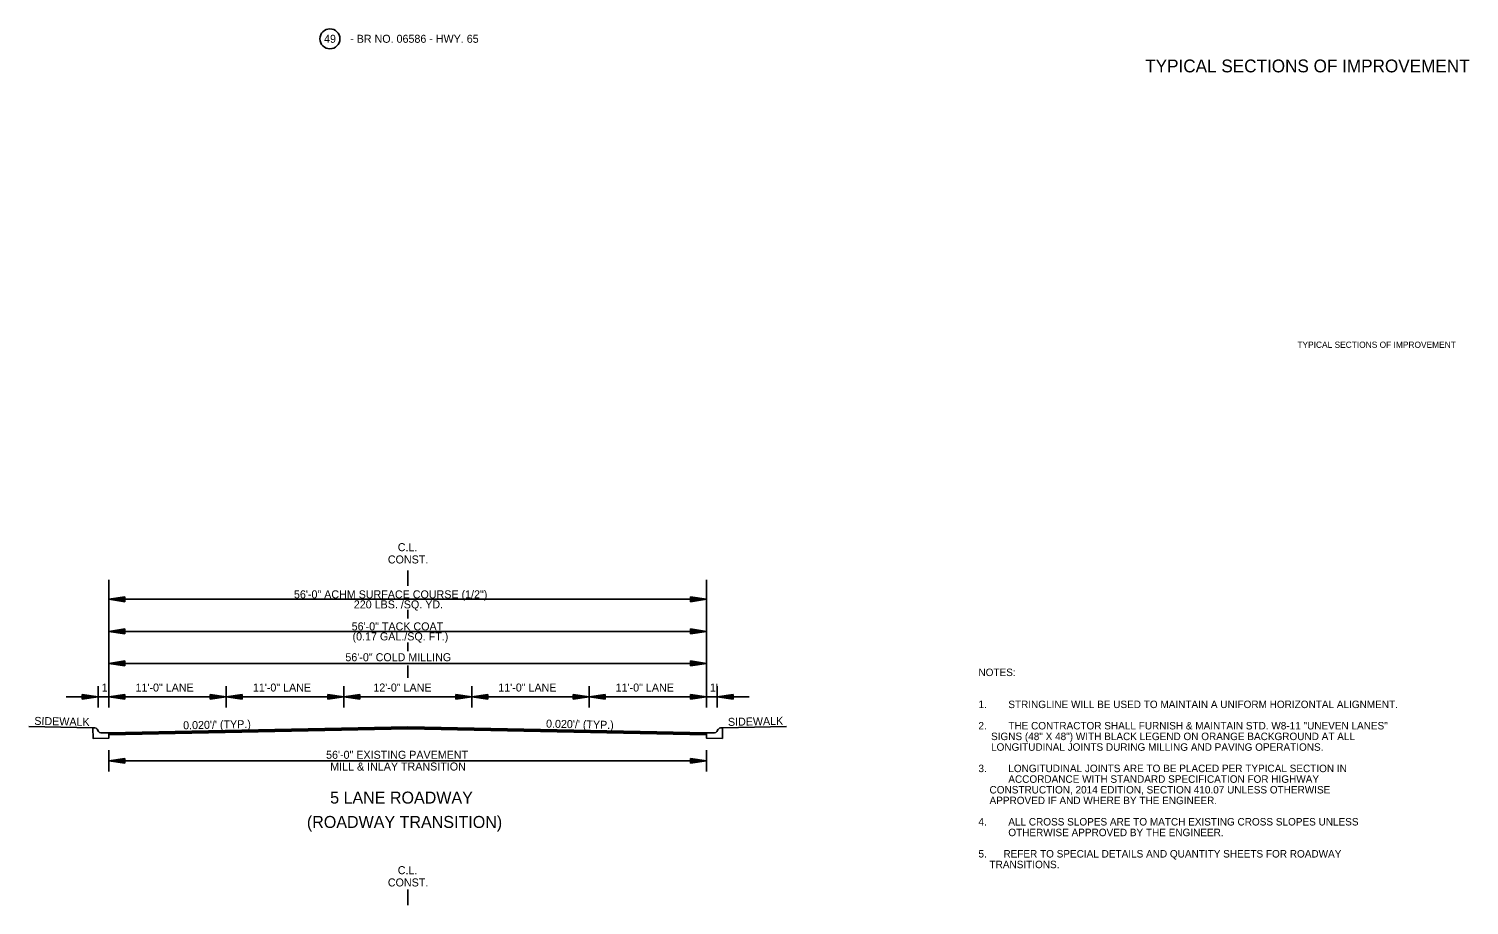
# Model space of a CAD drawing. Extents: x 550980 to 1930787, y -1972975 to 596640.
# Drawn here: x 551196 to 552546, y -1967506 to -1966685 of the extents above; entities that cross this region are included whole.
import ezdxf

# ---------------------------------------------------------------- set-up
doc = ezdxf.new("R2010")
doc.units = 0
for name, color, linetype in [('R_Border', 7, 'Continuous'), ('R_Border Notes', 7, 'Continuous'), ('R_Draft', 7, 'Continuous'), ('S_AREA_CALC', 7, 'Continuous')]:
    doc.layers.add(name, color=color, linetype=linetype)

# ---------------------------------------------------------------- blocks, each defined once
blk = doc.blocks.new('BPPOLY')
at = {"layer": 'R_Border'}
blk.add_circle((0, 0), 9.34, dxfattribs=at)

msp = doc.modelspace()

# ---------------------------------------------------------------- linework, layer by layer
at = {"layer": 'R_Border'}
for p, q in [((551551.1, -1967192), (551551.1, -1967206.5)), ((551286.1, -1967216.7), (551271.1, -1967219)), ((551271.1, -1967219), (551831.1, -1967219)), ((551286.1, -1967221.2), (551271.1, -1967219)), ((551286.1, -1967217.1), (551273.6, -1967219)), ((551286.1, -1967220.9), (551273.6, -1967219)), ((551286.1, -1967217.5), (551276.2, -1967219)), ((551286.1, -1967220.5), (551276.2, -1967219)), ((551286.1, -1967217.9), (551278.7, -1967219)), ((551286.1, -1967220.1), (551278.7, -1967219)), ((551286.1, -1967218.2), (551281.2, -1967219)), ((551286.1, -1967219.7), (551281.2, -1967219)), ((551286.1, -1967218.6), (551283.7, -1967219)), ((551286.1, -1967219.3), (551283.7, -1967219)), ((551286.1, -1967221.2), (551286.1, -1967216.7)), ((551816.1, -1967216.7), (551831.1, -1967219)), ((551816.1, -1967216.7), (551816.1, -1967221.2)), ((551816.1, -1967217.1), (551828.6, -1967219)), ((551816.1, -1967217.5), (551826, -1967219)), ((551816.1, -1967217.9), (551823.5, -1967219)), ((551816.1, -1967218.3), (551821, -1967219)), ((551816.1, -1967218.6), (551818.5, -1967219)), ((551816.1, -1967221.2), (551831.1, -1967219)), ((551816.1, -1967219.7), (551821, -1967219)), ((551816.1, -1967220.5), (551826, -1967219)), ((551816.1, -1967220.9), (551828.6, -1967219)), ((551816.1, -1967220.1), (551823.5, -1967219)), ((551816.1, -1967219.3), (551818.5, -1967219)), ((551551.1, -1967228.9), (551551.1, -1967237.1)), ((551286.1, -1967246.7), (551271.1, -1967249)), ((551286.1, -1967247.1), (551273.6, -1967249)), ((551286.1, -1967247.5), (551276.2, -1967249)), ((551286.1, -1967247.9), (551278.7, -1967249)), ((551286.1, -1967248.2), (551281.2, -1967249)), ((551286.1, -1967251.2), (551286.1, -1967246.7)), ((551816.1, -1967246.7), (551831.1, -1967249)), ((551816.1, -1967246.7), (551816.1, -1967251.2)), ((551816.1, -1967247.1), (551828.6, -1967249)), ((551816.1, -1967247.5), (551826, -1967249)), ((551816.1, -1967247.9), (551823.5, -1967249)), ((551816.1, -1967248.3), (551821, -1967249)), ((551271.1, -1967249), (551831.1, -1967249)), ((551286.1, -1967251.2), (551271.1, -1967249)), ((551286.1, -1967250.9), (551273.6, -1967249)), ((551286.1, -1967250.5), (551276.2, -1967249)), ((551286.1, -1967250.1), (551278.7, -1967249)), ((551286.1, -1967249.7), (551281.2, -1967249)), ((551286.1, -1967248.6), (551283.7, -1967249)), ((551286.1, -1967249.3), (551283.7, -1967249)), ((551551.1, -1967259.4), (551551.1, -1967267.6)), ((551816.1, -1967248.6), (551818.5, -1967249)), ((551816.1, -1967251.2), (551831.1, -1967249)), ((551816.1, -1967249.7), (551821, -1967249)), ((551816.1, -1967250.5), (551826, -1967249)), ((551816.1, -1967250.9), (551828.6, -1967249)), ((551816.1, -1967250.1), (551823.5, -1967249)), ((551816.1, -1967249.3), (551818.5, -1967249)), ((551271.1, -1967279), (551831.1, -1967279)), ((551261.1, -1967300.4), (551261.1, -1967320.4)), ((551381.1, -1967300.4), (551381.1, -1967320.4)), ((551491.1, -1967300.4), (551491.1, -1967320.4)), ((551611.1, -1967300.4), (551611.1, -1967320.4)), ((551721.1, -1967300.4), (551721.1, -1967320.4)), ((551841.1, -1967300.4), (551841.1, -1967320.4)), ((551231.1, -1967310.4), (551871.1, -1967310.4)), ((551246.1, -1967308.1), (551261.1, -1967310.4)), ((551246.1, -1967308.1), (551246.1, -1967312.6)), ((551246.1, -1967308.5), (551258.6, -1967310.4)), ((551246.1, -1967308.9), (551256, -1967310.4)), ((551246.1, -1967309.3), (551253.5, -1967310.4)), ((551246.1, -1967309.7), (551251, -1967310.4)), ((551246.1, -1967310), (551248.5, -1967310.4)), ((551246.1, -1967312.6), (551261.1, -1967310.4)), ((551246.1, -1967311.1), (551251, -1967310.4)), ((551246.1, -1967311.9), (551256, -1967310.4)), ((551246.1, -1967312.3), (551258.6, -1967310.4)), ((551246.1, -1967311.5), (551253.5, -1967310.4)), ((551246.1, -1967310.7), (551248.5, -1967310.4)), ((551286.1, -1967308.1), (551271.1, -1967310.4)), ((551286.1, -1967312.6), (551271.1, -1967310.4)), ((551286.1, -1967308.5), (551273.6, -1967310.4)), ((551286.1, -1967312.3), (551273.6, -1967310.4)), ((551286.1, -1967308.9), (551276.2, -1967310.4)), ((551286.1, -1967311.9), (551276.2, -1967310.4)), ((551286.1, -1967309.3), (551278.7, -1967310.4)), ((551286.1, -1967311.5), (551278.7, -1967310.4)), ((551286.1, -1967309.7), (551281.2, -1967310.4)), ((551286.1, -1967311.1), (551281.2, -1967310.4)), ((551286.1, -1967310), (551283.7, -1967310.4)), ((551286.1, -1967310.7), (551283.7, -1967310.4)), ((551286.1, -1967312.6), (551286.1, -1967308.1)), ((551366.1, -1967308.1), (551381.1, -1967310.4)), ((551366.1, -1967308.1), (551366.1, -1967312.6)), ((551366.1, -1967308.5), (551378.6, -1967310.4)), ((551366.1, -1967308.9), (551376, -1967310.4)), ((551366.1, -1967309.3), (551373.5, -1967310.4)), ((551366.1, -1967309.7), (551371, -1967310.4)), ((551366.1, -1967310), (551368.5, -1967310.4)), ((551366.1, -1967312.6), (551381.1, -1967310.4)), ((551366.1, -1967311.1), (551371, -1967310.4)), ((551366.1, -1967311.9), (551376, -1967310.4)), ((551366.1, -1967312.3), (551378.6, -1967310.4)), ((551366.1, -1967311.5), (551373.5, -1967310.4)), ((551366.1, -1967310.7), (551368.5, -1967310.4)), ((551396.1, -1967308.1), (551381.1, -1967310.4)), ((551396.1, -1967312.6), (551381.1, -1967310.4)), ((551396.1, -1967308.5), (551383.6, -1967310.4)), ((551396.1, -1967312.3), (551383.6, -1967310.4)), ((551396.1, -1967308.9), (551386.2, -1967310.4)), ((551396.1, -1967311.9), (551386.2, -1967310.4)), ((551396.1, -1967309.3), (551388.7, -1967310.4)), ((551396.1, -1967311.5), (551388.7, -1967310.4)), ((551396.1, -1967309.7), (551391.2, -1967310.4)), ((551396.1, -1967311.1), (551391.2, -1967310.4)), ((551396.1, -1967310), (551393.7, -1967310.4)), ((551396.1, -1967310.7), (551393.7, -1967310.4)), ((551396.1, -1967312.6), (551396.1, -1967308.1)), ((551476.1, -1967308.1), (551491.1, -1967310.4)), ((551476.1, -1967308.1), (551476.1, -1967312.6)), ((551476.1, -1967308.5), (551488.6, -1967310.4)), ((551476.1, -1967308.9), (551486, -1967310.4)), ((551476.1, -1967309.3), (551483.5, -1967310.4)), ((551476.1, -1967309.7), (551481, -1967310.4)), ((551476.1, -1967310), (551478.5, -1967310.4)), ((551476.1, -1967312.6), (551491.1, -1967310.4)), ((551476.1, -1967311.1), (551481, -1967310.4)), ((551476.1, -1967311.9), (551486, -1967310.4)), ((551476.1, -1967312.3), (551488.6, -1967310.4)), ((551476.1, -1967311.5), (551483.5, -1967310.4)), ((551476.1, -1967310.7), (551478.5, -1967310.4)), ((551506.1, -1967308.1), (551491.1, -1967310.4)), ((551506.1, -1967312.6), (551491.1, -1967310.4)), ((551506.1, -1967308.5), (551493.6, -1967310.4)), ((551506.1, -1967312.3), (551493.6, -1967310.4)), ((551506.1, -1967308.9), (551496.2, -1967310.4)), ((551506.1, -1967311.9), (551496.2, -1967310.4)), ((551506.1, -1967309.3), (551498.7, -1967310.4)), ((551506.1, -1967311.5), (551498.7, -1967310.4)), ((551506.1, -1967309.7), (551501.2, -1967310.4)), ((551506.1, -1967311.1), (551501.2, -1967310.4)), ((551506.1, -1967310), (551503.7, -1967310.4)), ((551506.1, -1967310.7), (551503.7, -1967310.4)), ((551506.1, -1967312.6), (551506.1, -1967308.1)), ((551596.1, -1967308.1), (551611.1, -1967310.4)), ((551596.1, -1967308.1), (551596.1, -1967312.6)), ((551596.1, -1967308.5), (551608.6, -1967310.4)), ((551596.1, -1967308.9), (551606, -1967310.4)), ((551596.1, -1967309.3), (551603.5, -1967310.4)), ((551596.1, -1967309.7), (551601, -1967310.4)), ((551596.1, -1967310), (551598.5, -1967310.4)), ((551596.1, -1967312.6), (551611.1, -1967310.4)), ((551596.1, -1967311.1), (551601, -1967310.4)), ((551596.1, -1967311.9), (551606, -1967310.4)), ((551596.1, -1967312.3), (551608.6, -1967310.4)), ((551596.1, -1967311.5), (551603.5, -1967310.4)), ((551596.1, -1967310.7), (551598.5, -1967310.4)), ((551626.1, -1967308.1), (551611.1, -1967310.4)), ((551626.1, -1967312.6), (551611.1, -1967310.4)), ((551626.1, -1967308.5), (551613.6, -1967310.4)), ((551626.1, -1967312.3), (551613.6, -1967310.4)), ((551626.1, -1967308.9), (551616.2, -1967310.4)), ((551626.1, -1967311.9), (551616.2, -1967310.4)), ((551626.1, -1967309.3), (551618.7, -1967310.4)), ((551626.1, -1967311.5), (551618.7, -1967310.4)), ((551626.1, -1967309.7), (551621.2, -1967310.4)), ((551626.1, -1967311.1), (551621.2, -1967310.4)), ((551626.1, -1967310), (551623.7, -1967310.4)), ((551626.1, -1967310.7), (551623.7, -1967310.4)), ((551626.1, -1967312.6), (551626.1, -1967308.1)), ((551706.1, -1967308.1), (551721.1, -1967310.4)), ((551706.1, -1967308.1), (551706.1, -1967312.6)), ((551706.1, -1967308.5), (551718.6, -1967310.4)), ((551706.1, -1967308.9), (551716, -1967310.4)), ((551706.1, -1967309.3), (551713.5, -1967310.4)), ((551706.1, -1967309.7), (551711, -1967310.4)), ((551706.1, -1967310), (551708.5, -1967310.4)), ((551706.1, -1967312.6), (551721.1, -1967310.4)), ((551706.1, -1967311.1), (551711, -1967310.4)), ((551706.1, -1967311.9), (551716, -1967310.4)), ((551706.1, -1967312.3), (551718.6, -1967310.4)), ((551706.1, -1967311.5), (551713.5, -1967310.4)), ((551706.1, -1967310.7), (551708.5, -1967310.4)), ((551736.1, -1967308.1), (551721.1, -1967310.4)), ((551736.1, -1967312.6), (551721.1, -1967310.4)), ((551736.1, -1967308.5), (551723.6, -1967310.4)), ((551736.1, -1967312.3), (551723.6, -1967310.4)), ((551736.1, -1967308.9), (551726.2, -1967310.4)), ((551736.1, -1967311.9), (551726.2, -1967310.4)), ((551736.1, -1967309.3), (551728.7, -1967310.4)), ((551736.1, -1967311.5), (551728.7, -1967310.4)), ((551736.1, -1967309.7), (551731.2, -1967310.4)), ((551736.1, -1967311.1), (551731.2, -1967310.4)), ((551736.1, -1967310), (551733.7, -1967310.4)), ((551736.1, -1967310.7), (551733.7, -1967310.4)), ((551736.1, -1967312.6), (551736.1, -1967308.1)), ((551816.1, -1967308.1), (551831.1, -1967310.4)), ((551816.1, -1967308.1), (551816.1, -1967312.6)), ((551816.1, -1967308.5), (551828.6, -1967310.4)), ((551816.1, -1967308.9), (551826, -1967310.4)), ((551816.1, -1967309.3), (551823.5, -1967310.4)), ((551816.1, -1967309.7), (551821, -1967310.4)), ((551816.1, -1967310), (551818.5, -1967310.4)), ((551816.1, -1967312.6), (551831.1, -1967310.4)), ((551816.1, -1967311.1), (551821, -1967310.4)), ((551816.1, -1967311.9), (551826, -1967310.4)), ((551816.1, -1967312.3), (551828.6, -1967310.4)), ((551816.1, -1967311.5), (551823.5, -1967310.4)), ((551816.1, -1967310.7), (551818.5, -1967310.4)), ((551856.1, -1967308.1), (551841.1, -1967310.4)), ((551856.1, -1967312.6), (551841.1, -1967310.4)), ((551856.1, -1967308.5), (551843.6, -1967310.4)), ((551856.1, -1967312.3), (551843.6, -1967310.4)), ((551856.1, -1967308.9), (551846.2, -1967310.4)), ((551856.1, -1967311.9), (551846.2, -1967310.4)), ((551856.1, -1967309.3), (551848.7, -1967310.4)), ((551856.1, -1967311.5), (551848.7, -1967310.4)), ((551856.1, -1967309.7), (551851.2, -1967310.4)), ((551856.1, -1967311.1), (551851.2, -1967310.4)), ((551856.1, -1967310), (551853.7, -1967310.4)), ((551856.1, -1967310.7), (551853.7, -1967310.4)), ((551856.1, -1967312.6), (551856.1, -1967308.1)), ((551256, -1967339.3), (551196, -1967338.1)), ((551846.2, -1967339.3), (551906.2, -1967338.1)), ((551271.1, -1967360.4), (551271.1, -1967380.4)), ((551286.1, -1967368.1), (551271.1, -1967370.4)), ((551286.1, -1967368.5), (551273.6, -1967370.4)), ((551286.1, -1967368.9), (551276.2, -1967370.4)), ((551286.1, -1967369.3), (551278.7, -1967370.4)), ((551286.1, -1967369.7), (551281.2, -1967370.4)), ((551286.1, -1967372.6), (551286.1, -1967368.1)), ((551816.1, -1967368.1), (551831.1, -1967370.4)), ((551816.1, -1967368.1), (551816.1, -1967372.6)), ((551816.1, -1967368.5), (551828.6, -1967370.4)), ((551816.1, -1967368.9), (551826, -1967370.4)), ((551816.1, -1967369.3), (551823.5, -1967370.4)), ((551816.1, -1967369.7), (551821, -1967370.4)), ((551831.1, -1967360.4), (551831.1, -1967380.4)), ((551271.1, -1967370.4), (551831.1, -1967370.4)), ((551286.1, -1967372.6), (551271.1, -1967370.4)), ((551286.1, -1967372.3), (551273.6, -1967370.4)), ((551286.1, -1967371.9), (551276.2, -1967370.4)), ((551286.1, -1967371.5), (551278.7, -1967370.4)), ((551286.1, -1967371.1), (551281.2, -1967370.4)), ((551286.1, -1967370), (551283.7, -1967370.4)), ((551286.1, -1967370.7), (551283.7, -1967370.4)), ((551816.1, -1967370), (551818.5, -1967370.4)), ((551816.1, -1967372.6), (551831.1, -1967370.4)), ((551816.1, -1967371.1), (551821, -1967370.4)), ((551816.1, -1967371.9), (551826, -1967370.4)), ((551816.1, -1967372.3), (551828.6, -1967370.4)), ((551816.1, -1967371.5), (551823.5, -1967370.4)), ((551816.1, -1967370.7), (551818.5, -1967370.4)), ((551551.1, -1967491), (551551.1, -1967505.5))]:
    msp.add_line(p, q, dxfattribs=at)
for points in [[(551271.1, -1967344), (551551.1, -1967338.4), (551831.1, -1967344)], [(551271.1, -1967344.3), (551551.1, -1967338.7), (551831.1, -1967344.3)], [(551271.1, -1967344.6), (551551.1, -1967339), (551831.1, -1967344.6)], [(551271.1, -1967344.9), (551551.1, -1967339.3), (551831.1, -1967344.9)], [(551271.1, -1967345.2), (551551.1, -1967339.6), (551831.1, -1967345.2)], [(551271.1, -1967345.5), (551551.1, -1967339.9), (551831.1, -1967345.5)], [(551271.1, -1967345.8), (551551.1, -1967340.2), (551831.1, -1967345.8)]]:
    msp.add_lwpolyline(points, dxfattribs=at)
at = {"layer": 'R_Draft'}
for p, q in [((551271.1, -1967320.4), (551271.1, -1967200.6)), ((551831.1, -1967320.4), (551831.1, -1967200.6)), ((551286.1, -1967276.7), (551271.1, -1967279)), ((551286.1, -1967281.2), (551271.1, -1967279)), ((551286.1, -1967277.1), (551273.6, -1967279)), ((551286.1, -1967280.9), (551273.6, -1967279)), ((551286.1, -1967277.5), (551276.2, -1967279)), ((551286.1, -1967280.5), (551276.2, -1967279)), ((551286.1, -1967277.9), (551278.7, -1967279)), ((551286.1, -1967280.1), (551278.7, -1967279)), ((551286.1, -1967278.3), (551281.2, -1967279)), ((551286.1, -1967279.7), (551281.2, -1967279)), ((551286.1, -1967278.6), (551283.7, -1967279)), ((551286.1, -1967279.3), (551283.7, -1967279)), ((551286.1, -1967276.7), (551286.1, -1967281.2)), ((551551.1, -1967292.5), (551551.1, -1967281.1)), ((551816.1, -1967276.7), (551831.1, -1967279)), ((551816.1, -1967281.2), (551816.1, -1967276.7)), ((551816.1, -1967277.1), (551828.6, -1967279)), ((551816.1, -1967277.5), (551826, -1967279)), ((551816.1, -1967277.9), (551823.5, -1967279)), ((551816.1, -1967278.2), (551821, -1967279)), ((551816.1, -1967278.6), (551818.5, -1967279)), ((551816.1, -1967281.2), (551831.1, -1967279)), ((551816.1, -1967279.7), (551821, -1967279)), ((551816.1, -1967280.5), (551826, -1967279)), ((551816.1, -1967280.9), (551828.6, -1967279)), ((551816.1, -1967280.1), (551823.5, -1967279)), ((551816.1, -1967279.3), (551818.5, -1967279)), ((551257.7, -1967339.3), (551256, -1967339.3)), ((551259.9, -1967340.5), (551261.4, -1967342.9)), ((551842.2, -1967340.5), (551840.8, -1967342.9)), ((551844.4, -1967339.3), (551846.2, -1967339.3)), ((551263.6, -1967344.1), (551271.1, -1967344)), ((551838.6, -1967344.1), (551831.1, -1967344))]:
    msp.add_line(p, q, dxfattribs=at)
for points in [[(551256, -1967339.3), (551256.2, -1967349.3), (551271.1, -1967349), (551271.1, -1967344)], [(551846.2, -1967339.3), (551846, -1967349.3), (551831.1, -1967349), (551831.1, -1967344)]]:
    msp.add_lwpolyline(points, dxfattribs=at)
for centre, start, end in [((551257.8, -1967341.8), 30.944, 91.1458), ((551263.5, -1967341.6), 210.944, 271.1458), ((551838.6, -1967341.6), 268.8542, 329.056), ((551844.4, -1967341.8), 88.8542, 149.056)]:
    msp.add_arc(centre, 2.5, start, end, dxfattribs=at)

# ---------------------------------------------------------------- block references
at = {"layer": 'R_Border'}
msp.add_blockref('BPPOLY', (551478.2, -1966693.9), dxfattribs=at)

# ---------------------------------------------------------------- texts
for s, height, p in [('49', 7.5, (551472.7, -1966697.6)), ('- BR NO. 06586 - HWY. 65', 7.5, (551497.2, -1966697.6)), ('C.L.', 7.5, (551541.8, -1967173.9)), ('CONST.', 7.5, (551532.5, -1967185.4)), ('56\'-0" ACHM SURFACE COURSE (1/2")', 7.5, (551444.5, -1967218.1)), ('220 LBS. /SQ. YD.', 7.5, (551500.6, -1967227.5)), ('56\'-0" TACK COAT', 7.5, (551498.6, -1967248.1)), ('(0.17 GAL./SQ. FT.)', 7.5, (551499.4, -1967257.5)), ('56\'-0" COLD MILLING', 7.5, (551492.7, -1967277)), ("1'", 7.5, (551264.3, -1967305.4)), ('11\'-0" LANE', 7.5, (551296, -1967305.4)), ('11\'-0" LANE', 7.5, (551406, -1967305.4)), ('12\'-0" LANE', 7.5, (551518.9, -1967305.4)), ('11\'-0" LANE', 7.5, (551636, -1967305.4)), ('11\'-0" LANE', 7.5, (551746, -1967305.4)), ("1'", 7.5, (551834.3, -1967305.4)), ('56\'-0" EXISTING PAVEMENT', 7.5, (551474.6, -1967368.4)), ('MILL & INLAY TRANSITION', 7.5, (551478.5, -1967379.4)), ('5 LANE ROADWAY', 11.25, (551478.4, -1967410.4)), ('(ROADWAY TRANSITION)', 11.25, (551456.6, -1967433.2)), ('C.L.', 7.5, (551541.8, -1967476.5)), ('CONST.', 7.5, (551532.5, -1967488))]:
    msp.add_text(s, height=height, dxfattribs=at).set_placement(p)
for s, height, rotation, p in [('TYPICAL SECTIONS OF IMPROVEMENT', 12, 360, (552242.3, -1966725.3)), ('SIDEWALK', 7.5, 358.8542, (551201.1, -1967336.6)), ('SIDEWALK', 7.5, 1.1458, (551851.3, -1967337.6)), ("0.020'/' (TYP.)", 7.5, 1.1458, (551340.7, -1967340.8)), ("0.020'/' (TYP.)", 7.5, 358.8542, (551680.7, -1967339.2))]:
    msp.add_text(s, height=height, rotation=rotation, dxfattribs=at).set_placement(p)
at = {"layer": 'R_Border Notes'}
for s, p in [('NOTES: ', (552086, -1967290.9)), ('1.', (552086, -1967320.9)), ('STRINGLINE WILL BE USED TO MAINTAIN A UNIFORM HORIZONTAL ALIGNMENT.', (552114, -1967320.9)), ('2.', (552086, -1967340.9)), ('THE CONTRACTOR SHALL FURNISH & MAINTAIN STD. W8-11 "UNEVEN LANES" ', (552114, -1967340.9)), ('    SIGNS (48" X 48") WITH BLACK LEGEND ON ORANGE BACKGROUND AT ALL ', (552087.4, -1967350.9)), ('    LONGITUDINAL JOINTS DURING MILLING AND PAVING OPERATIONS.', (552087.4, -1967360.9)), ('3.', (552086, -1967380.9)), ('LONGITUDINAL JOINTS ARE TO BE PLACED PER TYPICAL SECTION IN ', (552114, -1967380.9)), ('    CONSTRUCTION, 2014 EDITION, SECTION 410.07 UNLESS OTHERWISE', (552086, -1967400.9)), ('ACCORDANCE WITH STANDARD SPECIFICATION FOR HIGHWAY', (552114, -1967390.9)), ('    APPROVED IF AND WHERE BY THE ENGINEER.', (552086, -1967410.9)), ('4.', (552086, -1967430.9)), ('ALL CROSS SLOPES ARE TO MATCH EXISTING CROSS SLOPES UNLESS ', (552114, -1967430.9)), ('OTHERWISE APPROVED BY THE ENGINEER.', (552114, -1967440.9)), ('5.      REFER TO SPECIAL DETAILS AND QUANTITY SHEETS FOR ROADWAY', (552086, -1967460.9)), ('    TRANSITIONS.', (552086, -1967470.9))]:
    msp.add_text(s, height=7, dxfattribs=at).set_placement(p)
at = {"layer": 'S_AREA_CALC'}
msp.add_text('TYPICAL SECTIONS OF IMPROVEMENT', height=5.862, rotation=360, dxfattribs=at).set_placement((552384.9, -1966983.4))

doc.saveas('drawing.dxf')
